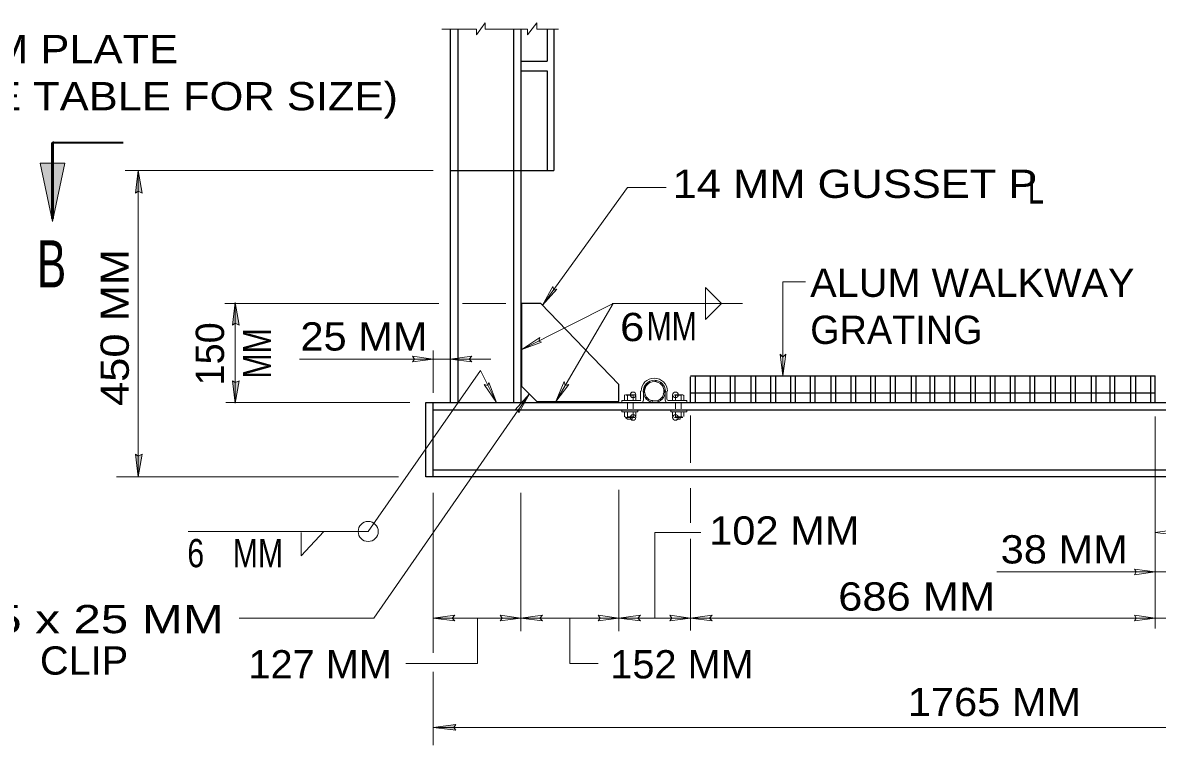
# Model space of a CAD drawing. Extents: x 312601.858 to 312602.699, y 144420.109 to 144420.704.
# Drawn here: x 312601.9234 to 312602.0438, y 144420.4578 to 144420.5345 of the extents above; entities that cross this region are included whole.
import ezdxf
from ezdxf.enums import TextEntityAlignment as Align

# ---------------------------------------------------------------- set-up
doc = ezdxf.new("R2010")
doc.units = 0
doc.header["$LTSCALE"] = 0.0012
doc.header["$PDMODE"] = 32
doc.header["$PDSIZE"] = 0.0006
doc.linetypes.add('LONG_DASHED', pattern=[7.5, 6, -1.5])
for name, color, linetype, lineweight in [('1', 7, 'Continuous', 13), ('2', 7, 'Continuous', 13), ('3', 7, 'Continuous', 13), ('39', 7, 'Continuous', 13), ('5', 7, 'Continuous', 25)]:
    doc.layers.add(name, color=color, linetype=linetype, lineweight=lineweight)

msp = doc.modelspace()

# ---------------------------------------------------------------- hatches: boundary and pattern name
at = {"layer": '1'}
for points in [[(312601.9253, 144420.5196), (312601.9266, 144420.5196), (312601.9266, 144420.5134)], [(312601.9253, 144420.5196), (312601.9266, 144420.5196), (312601.9266, 144420.5134)], [(312601.9279, 144420.5196), (312601.9266, 144420.5196), (312601.9266, 144420.5134)], [(312601.9279, 144420.5196), (312601.9266, 144420.5196), (312601.9266, 144420.5134)]]:
    msp.add_hatch(color=256, dxfattribs=at).paths.add_polyline_path(points)
at = {"layer": '39'}
for points in [[(312601.9357, 144420.5166), (312601.9354, 144420.5164), (312601.9357, 144420.5188), (312601.9361, 144420.5164)], [(312601.946, 144420.5026), (312601.9457, 144420.5024), (312601.946, 144420.5048), (312601.9464, 144420.5024)], [(312601.946, 144420.4963), (312601.9464, 144420.4965), (312601.946, 144420.4941), (312601.9457, 144420.4965)], [(312601.9357, 144420.4885), (312601.9361, 144420.4887), (312601.9357, 144420.4863), (312601.9354, 144420.4887)], [(312601.9692, 144420.4597), (312601.9694, 144420.4594), (312601.967, 144420.4597), (312601.9694, 144420.46)], [(312601.9692, 144420.4597), (312601.9694, 144420.4594), (312601.967, 144420.4597), (312601.9694, 144420.46)]]:
    msp.add_hatch(color=256, dxfattribs=at).paths.add_polyline_path(points)

# ---------------------------------------------------------------- linework, layer by layer
at = {"layer": '1'}
for p, q in [((312601.9679, 144420.5338), (312601.9716, 144420.5338)), ((312601.9716, 144420.5332), (312601.9725, 144420.5345)), ((312601.9716, 144420.5332), (312601.9716, 144420.5338)), ((312601.9725, 144420.5338), (312601.9725, 144420.5345)), ((312601.9725, 144420.5338), (312601.977, 144420.5338)), ((312601.977, 144420.5332), (312601.978, 144420.5345)), ((312601.977, 144420.5332), (312601.977, 144420.5338)), ((312601.978, 144420.5338), (312601.978, 144420.5345)), ((312601.978, 144420.5338), (312601.9803, 144420.5338)), ((312601.9265, 144420.5137), (312601.9265, 144420.5217)), ((312601.9343, 144420.5188), (312601.967, 144420.5188)), ((312601.9357, 144420.5188), (312601.9357, 144420.4863)), ((312602.0041, 144420.497), (312602.0041, 144420.507)), ((312602.0041, 144420.507), (312602.0065, 144420.507)), ((312601.9959, 144420.5064), (312601.9976, 144420.5047)), ((312601.9676, 144420.5047), (312601.9449, 144420.5047)), ((312601.946, 144420.5047), (312601.946, 144420.4942)), ((312601.9747, 144420.5047), (312601.9701, 144420.5047)), ((312601.9764, 144420.4998), (312601.9861, 144420.5047)), ((312601.9764, 144420.5047), (312601.9764, 144420.4959)), ((312601.98, 144420.4943), (312601.9861, 144420.5047)), ((312601.986, 144420.5047), (312601.9998, 144420.5047)), ((312601.9959, 144420.503), (312601.9976, 144420.5047)), ((312601.967, 144420.4952), (312601.967, 144420.4997)), ((312601.967, 144420.4988), (312601.9528, 144420.4988)), ((312601.9607, 144420.4713), (312601.9772, 144420.4951)), ((312601.945, 144420.4942), (312601.9645, 144420.4942)), ((312601.978, 144420.4943), (312601.9867, 144420.4943)), ((312601.9943, 144420.4878), (312601.9943, 144420.4928)), ((312602.0436, 144420.4702), (312602.0436, 144420.4927)), ((312601.9633, 144420.4863), (312601.9334, 144420.4863)), ((312601.967, 144420.4676), (312601.967, 144420.4846)), ((312601.9763, 144420.4846), (312601.9763, 144420.4699)), ((312601.9867, 144420.4699), (312601.9867, 144420.4849)), ((312601.9943, 144420.4814), (312601.9943, 144420.4851)), ((312601.941, 144420.4805), (312601.9601, 144420.4805)), ((312601.953, 144420.4804), (312601.953, 144420.4779)), ((312601.9943, 144420.47), (312601.9943, 144420.4797)), ((312601.9607, 144420.4713), (312601.9464, 144420.4713)), ((312601.967, 144420.4713), (312601.9763, 144420.4713)), ((312601.9763, 144420.4713), (312601.9867, 144420.4713)), ((312601.9867, 144420.4713), (312601.9943, 144420.4713)), ((312601.9943, 144420.4713), (312602.0436, 144420.4713)), ((312602.0436, 144420.4713), (312602.0888, 144420.4713)), ((312601.967, 144420.4578), (312601.967, 144420.4656)), ((312601.967, 144420.4597), (312602.0921, 144420.4597))]:
    msp.add_line(p, q, dxfattribs=at)
at = {"layer": '1', "lineweight": 25}
for p, q in [((312601.9688, 144420.5338), (312601.9688, 144420.4942)), ((312601.9696, 144420.5338), (312601.9696, 144420.4942)), ((312601.9755, 144420.5338), (312601.9755, 144420.4942)), ((312601.9763, 144420.5338), (312601.9763, 144420.4942)), ((312601.9791, 144420.5338), (312601.9791, 144420.5304)), ((312601.9798, 144420.5338), (312601.9798, 144420.5188)), ((312601.9763, 144420.5304), (312601.9791, 144420.5304)), ((312601.9763, 144420.5294), (312601.9791, 144420.5294)), ((312601.9791, 144420.5294), (312601.9791, 144420.5188)), ((312601.9688, 144420.5188), (312601.9798, 144420.5188)), ((312601.9784, 144420.5047), (312601.9764, 144420.5047)), ((312601.9784, 144420.5047), (312601.9867, 144420.4961)), ((312601.9867, 144420.4943), (312601.9867, 144420.4961)), ((312601.9943, 144420.497), (312602.0436, 144420.497)), ((312601.9943, 144420.4942), (312601.9943, 144420.4969)), ((312601.9948, 144420.497), (312601.9948, 144420.4942)), ((312601.9964, 144420.497), (312601.9964, 144420.4942)), ((312601.9969, 144420.497), (312601.9969, 144420.4942)), ((312601.9985, 144420.497), (312601.9985, 144420.4942)), ((312601.999, 144420.497), (312601.999, 144420.4942)), ((312602.0007, 144420.497), (312602.0007, 144420.4942)), ((312602.0012, 144420.497), (312602.0012, 144420.4942)), ((312602.0028, 144420.497), (312602.0028, 144420.4942)), ((312602.0033, 144420.497), (312602.0033, 144420.4942)), ((312602.0049, 144420.497), (312602.0049, 144420.4942)), ((312602.0054, 144420.497), (312602.0054, 144420.4942)), ((312602.007, 144420.497), (312602.007, 144420.4942)), ((312602.0075, 144420.497), (312602.0075, 144420.4942)), ((312602.0092, 144420.497), (312602.0092, 144420.4942)), ((312602.0097, 144420.497), (312602.0097, 144420.4942)), ((312602.0113, 144420.497), (312602.0113, 144420.4942)), ((312602.0118, 144420.497), (312602.0118, 144420.4942)), ((312602.0134, 144420.497), (312602.0134, 144420.4942)), ((312602.0139, 144420.497), (312602.0139, 144420.4942)), ((312602.0155, 144420.497), (312602.0155, 144420.4942)), ((312602.016, 144420.497), (312602.016, 144420.4942)), ((312602.0177, 144420.497), (312602.0177, 144420.4942)), ((312602.0182, 144420.497), (312602.0182, 144420.4942)), ((312602.0197, 144420.497), (312602.0197, 144420.4942)), ((312602.0202, 144420.497), (312602.0202, 144420.4942)), ((312602.0218, 144420.497), (312602.0218, 144420.4942)), ((312602.0223, 144420.497), (312602.0223, 144420.4942)), ((312602.024, 144420.497), (312602.024, 144420.4942)), ((312602.0245, 144420.497), (312602.0245, 144420.4942)), ((312602.0261, 144420.497), (312602.0261, 144420.4942)), ((312602.0266, 144420.497), (312602.0266, 144420.4942)), ((312602.0282, 144420.497), (312602.0282, 144420.4942)), ((312602.0287, 144420.497), (312602.0287, 144420.4942)), ((312602.0303, 144420.497), (312602.0303, 144420.4942)), ((312602.0308, 144420.497), (312602.0308, 144420.4942)), ((312602.0325, 144420.497), (312602.0325, 144420.4942)), ((312602.033, 144420.497), (312602.033, 144420.4942)), ((312602.0346, 144420.497), (312602.0346, 144420.4942)), ((312602.0351, 144420.497), (312602.0351, 144420.4942)), ((312602.0368, 144420.497), (312602.0368, 144420.4942)), ((312602.0373, 144420.497), (312602.0373, 144420.4942)), ((312602.0388, 144420.497), (312602.0388, 144420.4942)), ((312602.0393, 144420.497), (312602.0393, 144420.4942)), ((312602.041, 144420.497), (312602.041, 144420.4942)), ((312602.0415, 144420.497), (312602.0415, 144420.4942)), ((312602.0431, 144420.497), (312602.0431, 144420.4942)), ((312602.0436, 144420.4942), (312602.0436, 144420.497)), ((312601.9764, 144420.4959), (312601.978, 144420.4943)), ((312601.9943, 144420.4952), (312602.0436, 144420.4952)), ((312601.9662, 144420.4863), (312601.9662, 144420.4942)), ((312601.9662, 144420.4942), (312601.9917, 144420.4942)), ((312601.967, 144420.4863), (312601.967, 144420.4942)), ((312601.9917, 144420.4942), (312602.0929, 144420.4942)), ((312601.967, 144420.4934), (312602.0921, 144420.4934)), ((312602.0921, 144420.487), (312601.967, 144420.487)), ((312602.0929, 144420.4863), (312601.9662, 144420.4863))]:
    msp.add_line(p, q, dxfattribs=at)
at = {"layer": '1'}
for points in [[(312601.9267, 144420.5219), (312601.9267, 144420.5137), (312601.9265, 144420.5217)], [(312601.9786, 144420.5045), (312601.9876, 144420.517), (312601.9917, 144420.517)], [(312601.9731, 144420.4988), (312601.9688, 144420.4988), (312601.967, 144420.4988)], [(312601.9601, 144420.4805), (312601.972, 144420.4976), (312601.9737, 144420.4942)], [(312602.0268, 144420.4762), (312602.0436, 144420.4762), (312602.0458, 144420.4762), (312602.0511, 144420.4762)]]:
    msp.add_lwpolyline(points, dxfattribs=at)
at = {"layer": '1', "lineweight": 35}
msp.add_lwpolyline([(312601.9266, 144420.5196), (312601.9266, 144420.5218), (312601.9341, 144420.5218)], dxfattribs=at)
msp.add_lwpolyline([(312601.9266, 144420.5196), (312601.9266, 144420.5218), (312601.9341, 144420.5218)], dxfattribs=at)
at = {"layer": '1'}
for points in [[(312601.9253, 144420.5196), (312601.9266, 144420.5196), (312601.9266, 144420.5134)], [(312601.9253, 144420.5196), (312601.9266, 144420.5196), (312601.9266, 144420.5134)], [(312601.9279, 144420.5196), (312601.9266, 144420.5196), (312601.9266, 144420.5134)], [(312601.9279, 144420.5196), (312601.9266, 144420.5196), (312601.9266, 144420.5134)], [(312601.9801, 144420.5062), (312601.9786, 144420.5045), (312601.9797, 144420.5065), (312601.9798, 144420.5061)], [(312601.9785, 144420.5006), (312601.9764, 144420.4998), (312601.9783, 144420.5011), (312601.9782, 144420.5007)], [(312601.9648, 144420.4991), (312601.967, 144420.4988), (312601.9648, 144420.4985), (312601.965, 144420.4988)], [(312601.9711, 144420.4985), (312601.9688, 144420.4988), (312601.9711, 144420.4991), (312601.9708, 144420.4988)], [(312602.0044, 144420.4993), (312602.0041, 144420.497), (312602.0038, 144420.4993), (312602.0041, 144420.499)], [(312601.9729, 144420.4963), (312601.9737, 144420.4942), (312601.9724, 144420.4961), (312601.9728, 144420.496)], [(312601.9814, 144420.4961), (312601.98, 144420.4943), (312601.9809, 144420.4964), (312601.981, 144420.496)], [(312601.9757, 144420.4934), (312601.9772, 144420.4951), (312601.9761, 144420.4931), (312601.976, 144420.4934)], [(312602.0459, 144420.4801), (312602.0436, 144420.4804), (312602.0459, 144420.4807), (312602.0456, 144420.4804)], [(312602.0414, 144420.4765), (312602.0436, 144420.4762), (312602.0414, 144420.4759), (312602.0416, 144420.4762)], [(312601.9693, 144420.471), (312601.967, 144420.4713), (312601.9693, 144420.4716), (312601.969, 144420.4713)], [(312601.9741, 144420.4716), (312601.9763, 144420.4713), (312601.9741, 144420.471), (312601.9743, 144420.4713)], [(312601.9786, 144420.471), (312601.9763, 144420.4713), (312601.9786, 144420.4716), (312601.9783, 144420.4713)], [(312601.9845, 144420.4716), (312601.9867, 144420.4713), (312601.9845, 144420.471), (312601.9847, 144420.4713)], [(312601.989, 144420.471), (312601.9867, 144420.4713), (312601.989, 144420.4716), (312601.9887, 144420.4713)], [(312601.9921, 144420.4716), (312601.9943, 144420.4713), (312601.9921, 144420.471), (312601.9923, 144420.4713)], [(312601.9966, 144420.471), (312601.9943, 144420.4713), (312601.9966, 144420.4716), (312601.9963, 144420.4713)], [(312602.0414, 144420.4716), (312602.0436, 144420.4713), (312602.0414, 144420.471), (312602.0416, 144420.4713)]]:
    msp.add_lwpolyline(points, close=True, dxfattribs=at)
at = {"layer": '2'}
for p, q in [((312601.9905, 144420.4804), (312601.9905, 144420.4713)), ((312601.9905, 144420.4804), (312601.9954, 144420.4804)), ((312601.9717, 144420.4713), (312601.9717, 144420.4665)), ((312601.9641, 144420.4665), (312601.9717, 144420.4665))]:
    msp.add_line(p, q, dxfattribs=at)
for points in [[(312601.9959, 144420.503), (312601.9959, 144420.5047), (312601.9959, 144420.5064)], [(312601.9815, 144420.4713), (312601.9815, 144420.4665), (312601.9845, 144420.4665)]]:
    msp.add_lwpolyline(points, dxfattribs=at)
msp.add_circle((312601.9601, 144420.4805), 0.001063, dxfattribs=at)
at = {"layer": '3'}
for p, q in [((312601.9893, 144420.4955), (312601.9898, 144420.4963)), ((312601.9899, 144420.4962), (312601.99, 144420.4965)), ((312601.9873, 144420.495), (312601.9873, 144420.4944)), ((312601.9884, 144420.495), (312601.9874, 144420.495)), ((312601.9876, 144420.495), (312601.9876, 144420.4944)), ((312601.9882, 144420.495), (312601.9882, 144420.4944)), ((312601.9885, 144420.4949), (312601.9885, 144420.4944)), ((312601.9893, 144420.4954), (312601.9893, 144420.4944)), ((312601.9893, 144420.4952), (312601.9894, 144420.4954)), ((312601.9914, 144420.4951), (312601.9916, 144420.4954)), ((312601.9915, 144420.4954), (312601.9916, 144420.4956)), ((312601.9916, 144420.4954), (312601.9916, 144420.4944)), ((312601.9924, 144420.495), (312601.9924, 144420.4944)), ((312601.9926, 144420.495), (312601.9935, 144420.495)), ((312601.9927, 144420.495), (312601.9927, 144420.4944)), ((312601.9933, 144420.495), (312601.9933, 144420.4944)), ((312601.9936, 144420.4949), (312601.9936, 144420.4944)), ((312601.987, 144420.4944), (312601.989, 144420.4944)), ((312601.987, 144420.4942), (312601.987, 144420.4944)), ((312601.9873, 144420.4944), (312601.9879, 144420.4944)), ((312601.9885, 144420.4944), (312601.9879, 144420.4944)), ((312601.9882, 144420.4942), (312601.9891, 144420.4942)), ((312601.9891, 144420.4942), (312601.9955, 144420.4942)), ((312601.9908, 144420.4942), (312601.9909, 144420.4944)), ((312601.991, 144420.4943), (312601.9912, 144420.4946)), ((312601.9939, 144420.4944), (312601.9919, 144420.4944)), ((312601.9924, 144420.4944), (312601.993, 144420.4944)), ((312601.9933, 144420.4942), (312601.9927, 144420.4942)), ((312601.9936, 144420.4944), (312601.993, 144420.4944)), ((312601.9939, 144420.4942), (312601.9939, 144420.4944)), ((312601.987, 144420.4932), (312601.987, 144420.4934)), ((312601.9873, 144420.4927), (312601.9873, 144420.4932)), ((312601.9873, 144420.4932), (312601.9879, 144420.4932)), ((312601.9876, 144420.4927), (312601.9876, 144420.4932)), ((312601.9876, 144420.4924), (312601.9881, 144420.4924)), ((312601.9885, 144420.4932), (312601.9879, 144420.4932)), ((312601.9881, 144420.4926), (312601.9881, 144420.4924)), ((312601.9882, 144420.4927), (312601.9882, 144420.4932)), ((312601.9885, 144420.4927), (312601.9885, 144420.4932)), ((312601.9922, 144420.4932), (312601.9922, 144420.4934)), ((312601.9939, 144420.4932), (312601.9922, 144420.4932)), ((312601.9924, 144420.4927), (312601.9924, 144420.4932)), ((312601.9924, 144420.4932), (312601.993, 144420.4932)), ((312601.9926, 144420.4926), (312601.9935, 144420.4926)), ((312601.9927, 144420.4927), (312601.9927, 144420.4932)), ((312601.9932, 144420.4924), (312601.9928, 144420.4924)), ((312601.9936, 144420.4932), (312601.993, 144420.4932)), ((312601.9933, 144420.4927), (312601.9933, 144420.4932)), ((312601.9936, 144420.4927), (312601.9936, 144420.4932)), ((312601.9939, 144420.4932), (312601.9939, 144420.4934))]:
    msp.add_line(p, q, dxfattribs=at)
at = {"layer": '3', "linetype": 'LONG_DASHED'}
for p, q in [((312601.9876, 144420.4942), (312601.9876, 144420.4935)), ((312601.9882, 144420.4942), (312601.9882, 144420.4935)), ((312601.9927, 144420.4942), (312601.9927, 144420.4935)), ((312601.9933, 144420.4942), (312601.9933, 144420.4935))]:
    msp.add_line(p, q, dxfattribs=at)
at = {"layer": '3'}
for points in [[(312601.9906, 144420.4964), (312601.9906, 144420.4965), (312601.9908, 144420.4965)], [(312601.9912, 144420.4962), (312601.9912, 144420.4963), (312601.9913, 144420.4962)], [(312601.989, 144420.4954), (312601.989, 144420.4952), (312601.989, 144420.4945)], [(312601.9896, 144420.4945), (312601.9897, 144420.4947), (312601.9896, 144420.4948)], [(312601.9918, 144420.4954), (312601.9918, 144420.4952), (312601.9918, 144420.4945)], [(312601.9855, 144420.4942), (312601.9876, 144420.4942), (312601.9882, 144420.4942)], [(312601.9902, 144420.4942), (312601.9903, 144420.4944), (312601.9901, 144420.4944)], [(312601.9928, 144420.4942), (312601.9918, 144420.4942), (312601.9915, 144420.4942)], [(312601.987, 144420.4932), (312601.9887, 144420.4932), (312601.9887, 144420.4934)], [(312601.9884, 144420.4926), (312601.9874, 144420.4926), (312601.9876, 144420.4924)], [(312601.9932, 144420.4926), (312601.9932, 144420.4924), (312601.9928, 144420.4924)]]:
    msp.add_lwpolyline(points, dxfattribs=at)
for radius in [0.001175, 0.00103]:
    msp.add_circle((312601.990455, 144420.495376), radius, dxfattribs=at)
for centre, radius, start, end in [((312601.990455, 144420.495376), 0.001399, 0, 180), ((312601.988977, 144420.494465), 0.0000792, 270, 0), ((312601.989082, 144420.494399), 0.000198, 270, 0), ((312601.991828, 144420.494399), 0.000198, 180, 270), ((312601.991934, 144420.494465), 0.0000792, 180, 270)]:
    msp.add_arc(centre, radius, start, end, dxfattribs=at)
for centre, major_axis, start_param, end_param in [((312601.987428, 144420.494751), (0.000267, 0), 0.970898, 2.1858445), ((312601.987893, 144420.494071), (0.001082, 0), 1.2763403, 1.8649531), ((312601.987882, 144420.493695), (-0.001534, 0), 4.4986502, 4.498801), ((312601.988358, 144420.494751), (0.000267, 0), 0.9448732, 2.1695573), ((312601.988835, 144420.493695), (0.001534, 0), 1.7843843, 1.7845351), ((312601.992076, 144420.493695), (-0.001534, 0), 4.4986502, 4.5023266), ((312601.992552, 144420.494751), (-0.000267, 0), 4.113628, 5.3383121), ((312601.993017, 144420.494071), (-0.001082, 0), 4.4182323, 5.006845), ((312601.993029, 144420.493695), (0.001534, 0), 1.7843843, 1.7845351), ((312601.993482, 144420.494751), (-0.000267, 0), 4.0973408, 5.3122873), ((312601.987428, 144420.492882), (0.000267, 0), 4.0973408, 5.3122873), ((312601.987893, 144420.493561), (0.001082, 0), 4.4182323, 5.006845), ((312601.988358, 144420.492882), (0.000267, 0), 4.113628, 5.3383121), ((312601.987882, 144420.493938), (-0.001534, 0), 1.7843843, 1.7845351), ((312601.992552, 144420.492882), (-0.000267, 0), 0.9448732, 2.1695573), ((312601.993017, 144420.493561), (-0.001082, 0), 1.2763403, 1.8649531), ((312601.993482, 144420.492882), (-0.000267, 0), 0.970898, 2.1858445)]:
    msp.add_ellipse(centre, major_axis=major_axis, ratio=0.83375, start_param=start_param, end_param=end_param, dxfattribs=at)
for p in [(312601.9882, 144420.495), (312601.9927, 144420.495), (312601.9882, 144420.4926), (312601.9927, 144420.4926)]:
    msp.add_point(p, dxfattribs=at)
at = {"layer": '39'}
for points in [[(312601.9357, 144420.5166), (312601.9354, 144420.5164), (312601.9357, 144420.5188), (312601.9361, 144420.5164)], [(312601.946, 144420.5026), (312601.9457, 144420.5024), (312601.946, 144420.5048), (312601.9464, 144420.5024)], [(312601.946, 144420.4963), (312601.9464, 144420.4965), (312601.946, 144420.4941), (312601.9457, 144420.4965)], [(312601.9357, 144420.4885), (312601.9361, 144420.4887), (312601.9357, 144420.4863), (312601.9354, 144420.4887)], [(312601.9692, 144420.4597), (312601.9694, 144420.4594), (312601.967, 144420.4597), (312601.9694, 144420.46)], [(312601.9692, 144420.4597), (312601.9694, 144420.4594), (312601.967, 144420.4597), (312601.9694, 144420.46)]]:
    msp.add_lwpolyline(points, close=True, dxfattribs=at)
at = {"layer": '5', "lineweight": 13}
msp.add_line((312601.953, 144420.4779), (312601.9554, 144420.4805), dxfattribs=at)

# ---------------------------------------------------------------- texts
at = {"layer": '2'}
for s, width, p in [('SHIM PLATE', 1.15, (312601.9125, 144420.5302)), ('(SEE TABLE FOR SIZE)', 1.15, (312601.9125, 144420.5252)), ('14 MM GUSSET P', 1.15, (312601.9924, 144420.5159)), ('ALUM WALKWAY', 1.05, (312602.007, 144420.5054))]:
    msp.add_text(s, height=0.003, dxfattribs=dict(at, width=width)).set_placement(p)
for s, height, width, p in [('L', 0.003, 0.75, (312602.03095, 144420.5153)), ('B', 0.005, 0.7, (312601.9265, 144420.5064)), ('6 ', 0.003, 1.15, (312601.98875, 144420.5007)), ('MM', 0.003, 0.8, (312601.9923, 144420.5008)), ('25 MM', 0.003, 1.1, (312601.95965, 144420.4997)), ('102 MM', 0.003, 1.1, (312602.00425, 144420.4791)), ('6', 0.003, 0.8, (312601.9418, 144420.4767)), ('MM', 0.003, 0.8, (312601.9484, 144420.4767)), ('38 MM', 0.003, 1.1, (312602.03395, 144420.4771)), ('686 MM', 0.003, 1.15, (312602.0183, 144420.4721)), ('25 x 25 MM', 0.003, 1.3, (312601.93115, 144420.4697)), ('CLIP', 0.003, 1.05, (312601.92995, 144420.4653)), ('127 MM', 0.003, 1.05, (312601.955, 144420.4649)), ('152 MM', 0.003, 1.05, (312601.9934, 144420.4649)), ('1765 MM', 0.003, 1.1, (312602.02655, 144420.4609))]:
    msp.add_text(s, height=height, dxfattribs=dict(at, width=width)).set_placement(p, align=Align.CENTER)
for s, width, p in [('450 MM', 1.15, (312601.9347, 144420.50215)), ('MM', 0.8, (312601.9498, 144420.4994))]:
    msp.add_text(s, height=0.003, rotation=90, dxfattribs=dict(at, width=width)).set_placement(p, align=Align.CENTER)
msp.add_text('GRATING', height=0.003, dxfattribs=at).set_placement((312602.007, 144420.5004))
msp.add_text('150', height=0.003, rotation=90, dxfattribs=at).set_placement((312601.9448, 144420.49935), align=Align.CENTER)

doc.saveas('drawing.dxf')
